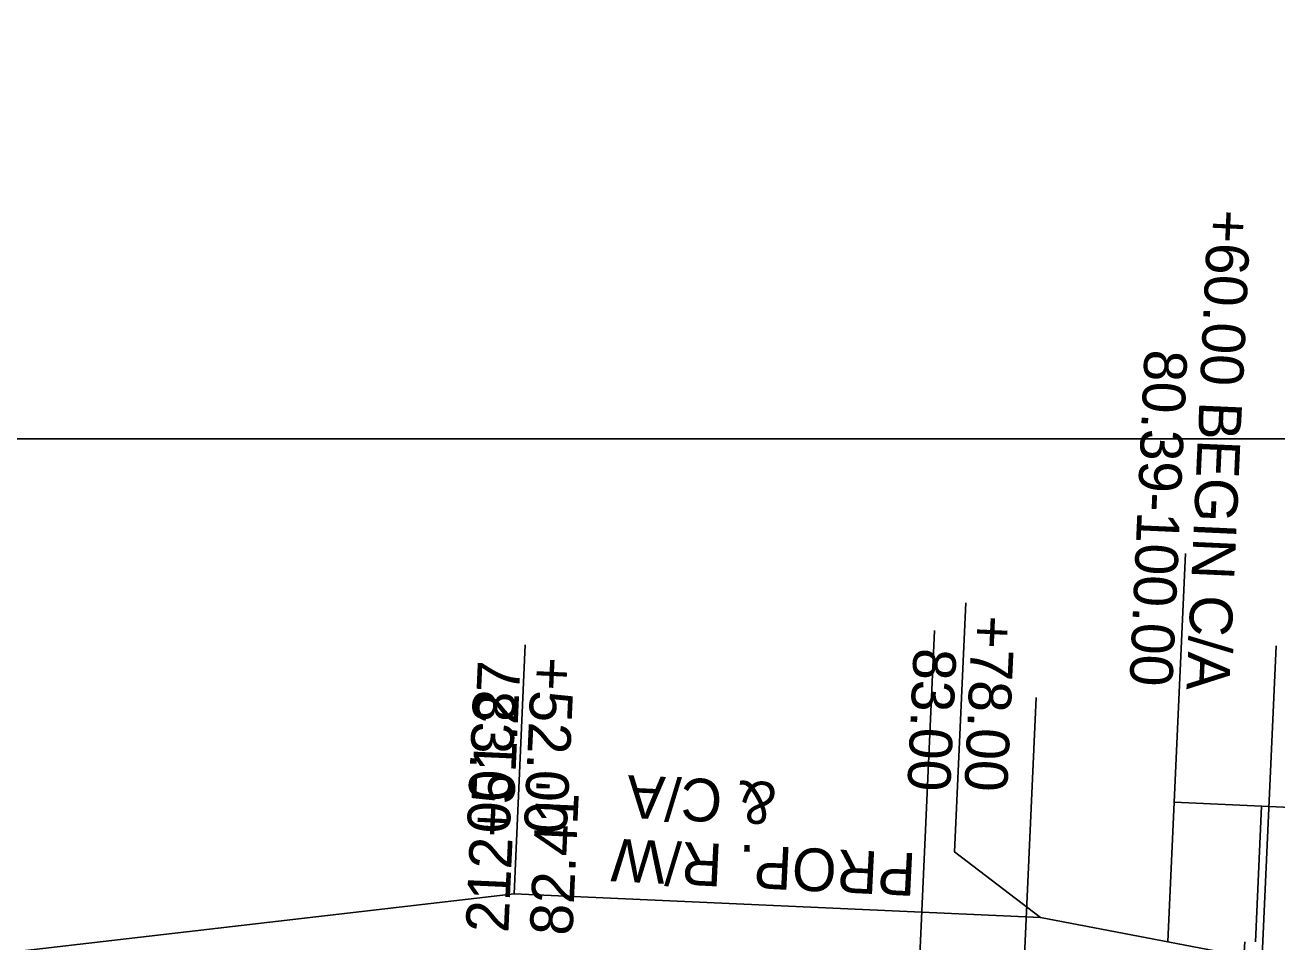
# Model space of a CAD drawing. Extents: x -70 to 701944, y -4 to 666871.
# Drawn here: x 666876 to 667051.7, y 656671.2 to 656800 of the extents above; entities that cross this region are included whole.
import ezdxf

# ---------------------------------------------------------------- set-up
doc = ezdxf.new("R2010")
doc.units = 0
for name, color, linetype in [('R_Detour', 7, 'Continuous'), ('R_Draft', 7, 'Continuous'), ('R_Drive', 7, 'Continuous'), ('R_No Plot', 7, 'Continuous'), ('R_ROW', 7, 'Continuous'), ('R_ROW Annot', 7, 'Continuous'), ('R_Temp Easement', 7, 'Continuous')]:
    doc.layers.add(name, color=color, linetype=linetype)

msp = doc.modelspace()

# ---------------------------------------------------------------- linework, layer by layer
at = {"layer": 'R_Detour'}
for p, q in [((668023.64, 656741.87), (666796.56, 656741.87)), ((667017.94, 656705.53), (667012.81, 656591.81))]:
    msp.add_line(p, q, dxfattribs=at)
at = {"layer": 'R_Draft'}
for p, q in [((666992.97, 656478.62), (667003.65, 656714.95)), ((667040.92, 656476.46), (667051.6, 656712.79))]:
    msp.add_line(p, q, dxfattribs=at)
at = {"layer": 'R_Drive'}
msp.add_line((667049.58, 656690.25), (667048.72, 656671.21), dxfattribs=at)
msp.add_arc((667017.75, 656672.55), 29.5, 270.8221, 357.413, dxfattribs=at)
at = {"layer": 'R_ROW'}
msp.add_lwpolyline([(668183.45, 656677.29), (668041.7, 656619.63), (667513.59, 656642.26), (667480, 656629.76), (667392.27, 656637.73), (667276.83, 656674.98), (667204.95, 656679.23), (667093.98, 656660.22), (667018.55, 656674.64), (666944.63, 656677.98), (666832.93, 656665.01), (666352.77, 656716.73), (665777.5, 656723.7), (665727.42, 656722.96), (665452.7, 656735.37), (665090.34, 656757.75), (665090.29, 656778.78), (664696.26, 656796.57), (664695.54, 656784.55), (664566.62, 656799.96)], dxfattribs=at)
at = {"layer": 'R_ROW Annot'}
for points in [[(667037.3, 656690.81), (667038.88, 656725.77)], [(667018.55, 656674.64), (667006.47, 656683.85), (667008.05, 656718.82)], [(666944.63, 656677.98), (666946.21, 656712.94)]]:
    msp.add_lwpolyline(points, dxfattribs=at)
at = {"layer": 'R_Temp Easement'}
for q in [(667036.41, 656671.22), (667087.25, 656688.55)]:
    msp.add_line((667037.3, 656690.81), q, dxfattribs=at)

# ---------------------------------------------------------------- texts
at = {"layer": 'R_No Plot'}
for s, p in [('212+51.27 ', (666943.83, 656672.42)), ("82.41' ", (666952.82, 656672.02))]:
    msp.add_text(s, height=6, rotation=87.4131, dxfattribs=at).set_placement(p)
at = {"layer": 'R_ROW'}
for s, p in [('& C/A', (666981.57, 656693.61)), ('PROP. R/W ', (667001.18, 656683.64))]:
    msp.add_text(s, height=6, rotation=177.2014, dxfattribs=at).set_placement(p)
at = {"layer": 'R_ROW Annot'}
for s, p in [('+60.00 BEGIN C/A', (667042.07, 656774.15)), ('80.39-100.00', (667033.17, 656754.47)), ('+78.00', (667008.97, 656717.18)), ('83.00', (667000.75, 656712.55)), ('+52.00', (666947.13, 656711.31)), ('83.00', (666938.92, 656706.67))]:
    msp.add_text(s, height=6, rotation=267.4131, dxfattribs=at).set_placement(p)

doc.saveas('drawing.dxf')
